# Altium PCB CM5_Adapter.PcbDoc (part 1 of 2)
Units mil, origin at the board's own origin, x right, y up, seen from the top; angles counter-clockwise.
Board outline 2180 x 1650 mil, 4 copper layers (Top Layer, Sig1, Sig2, Bottom Layer), stack 50.112 mil thick; 16 components, 251 nets, 1069 pads, 196 vias.
Unrouted connection lines stored in the file: 3.
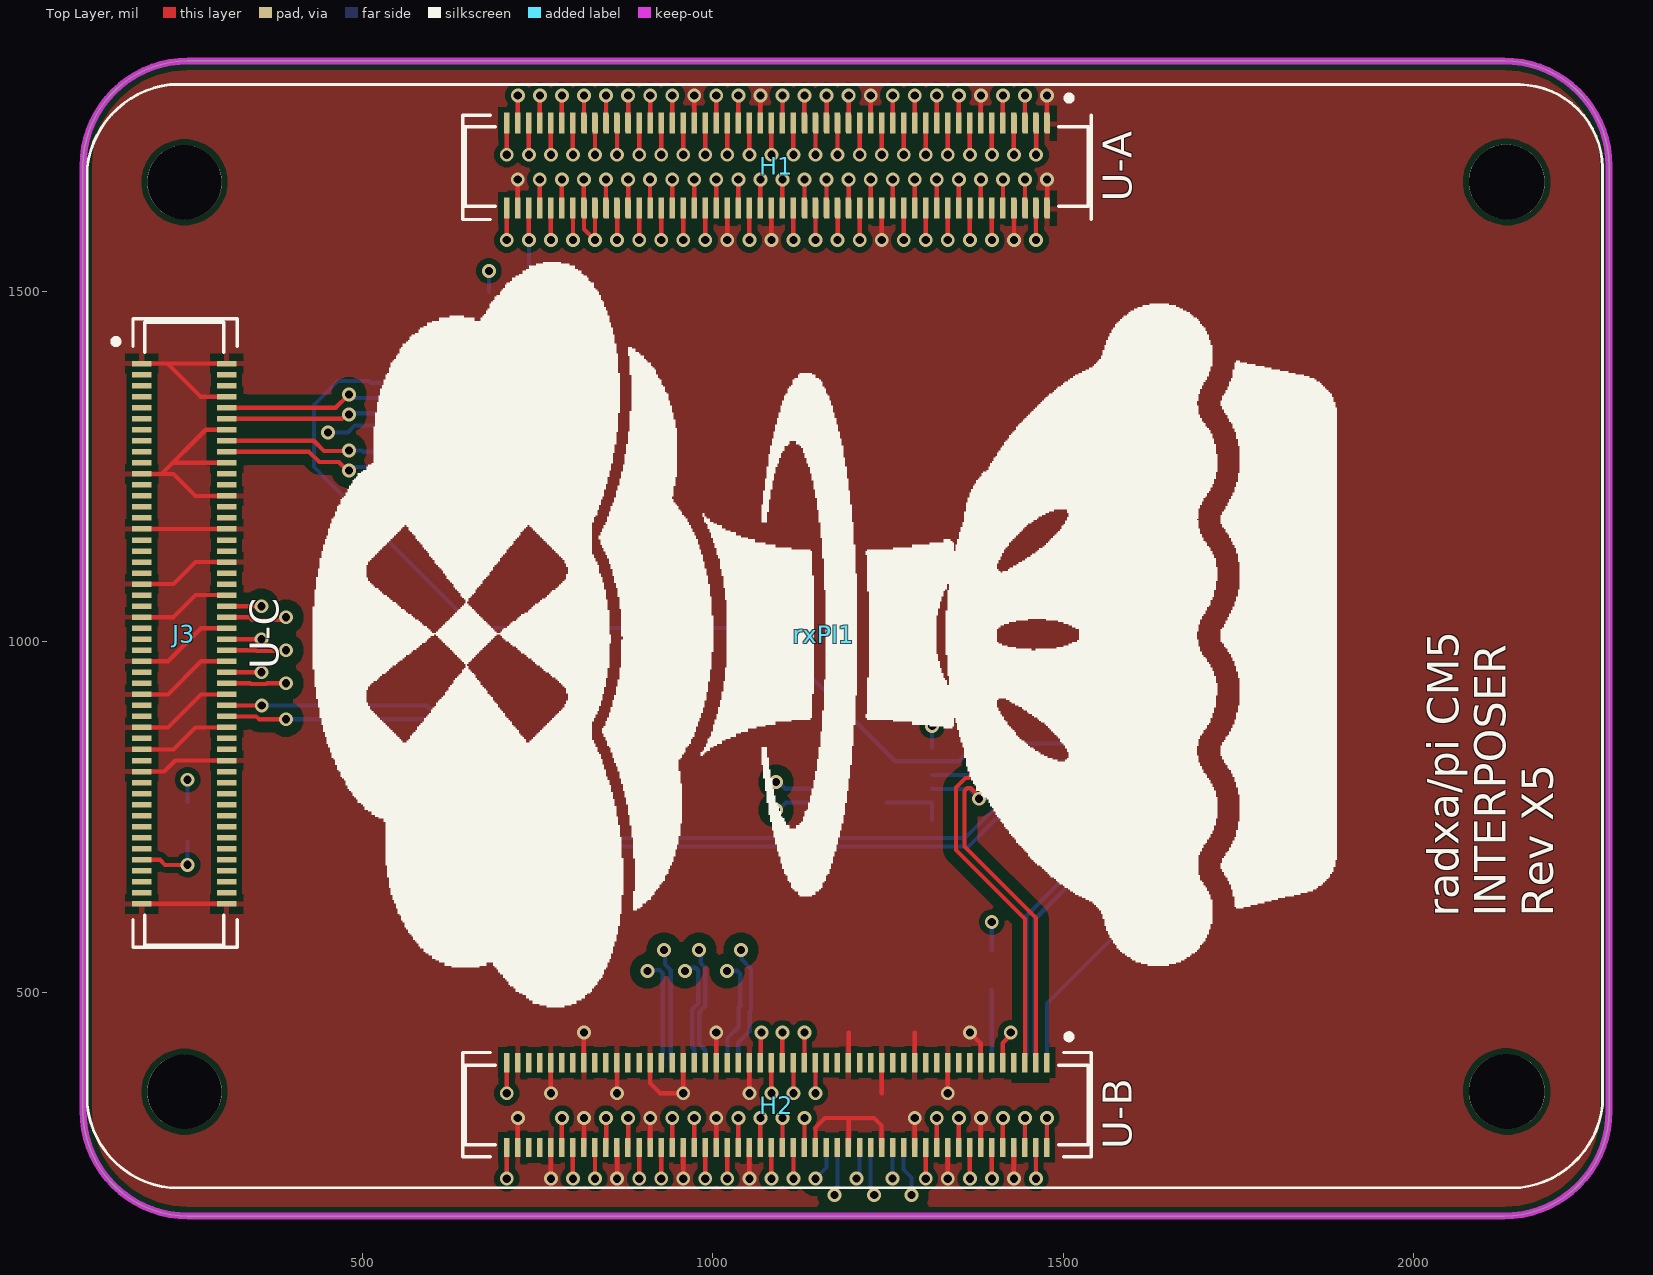
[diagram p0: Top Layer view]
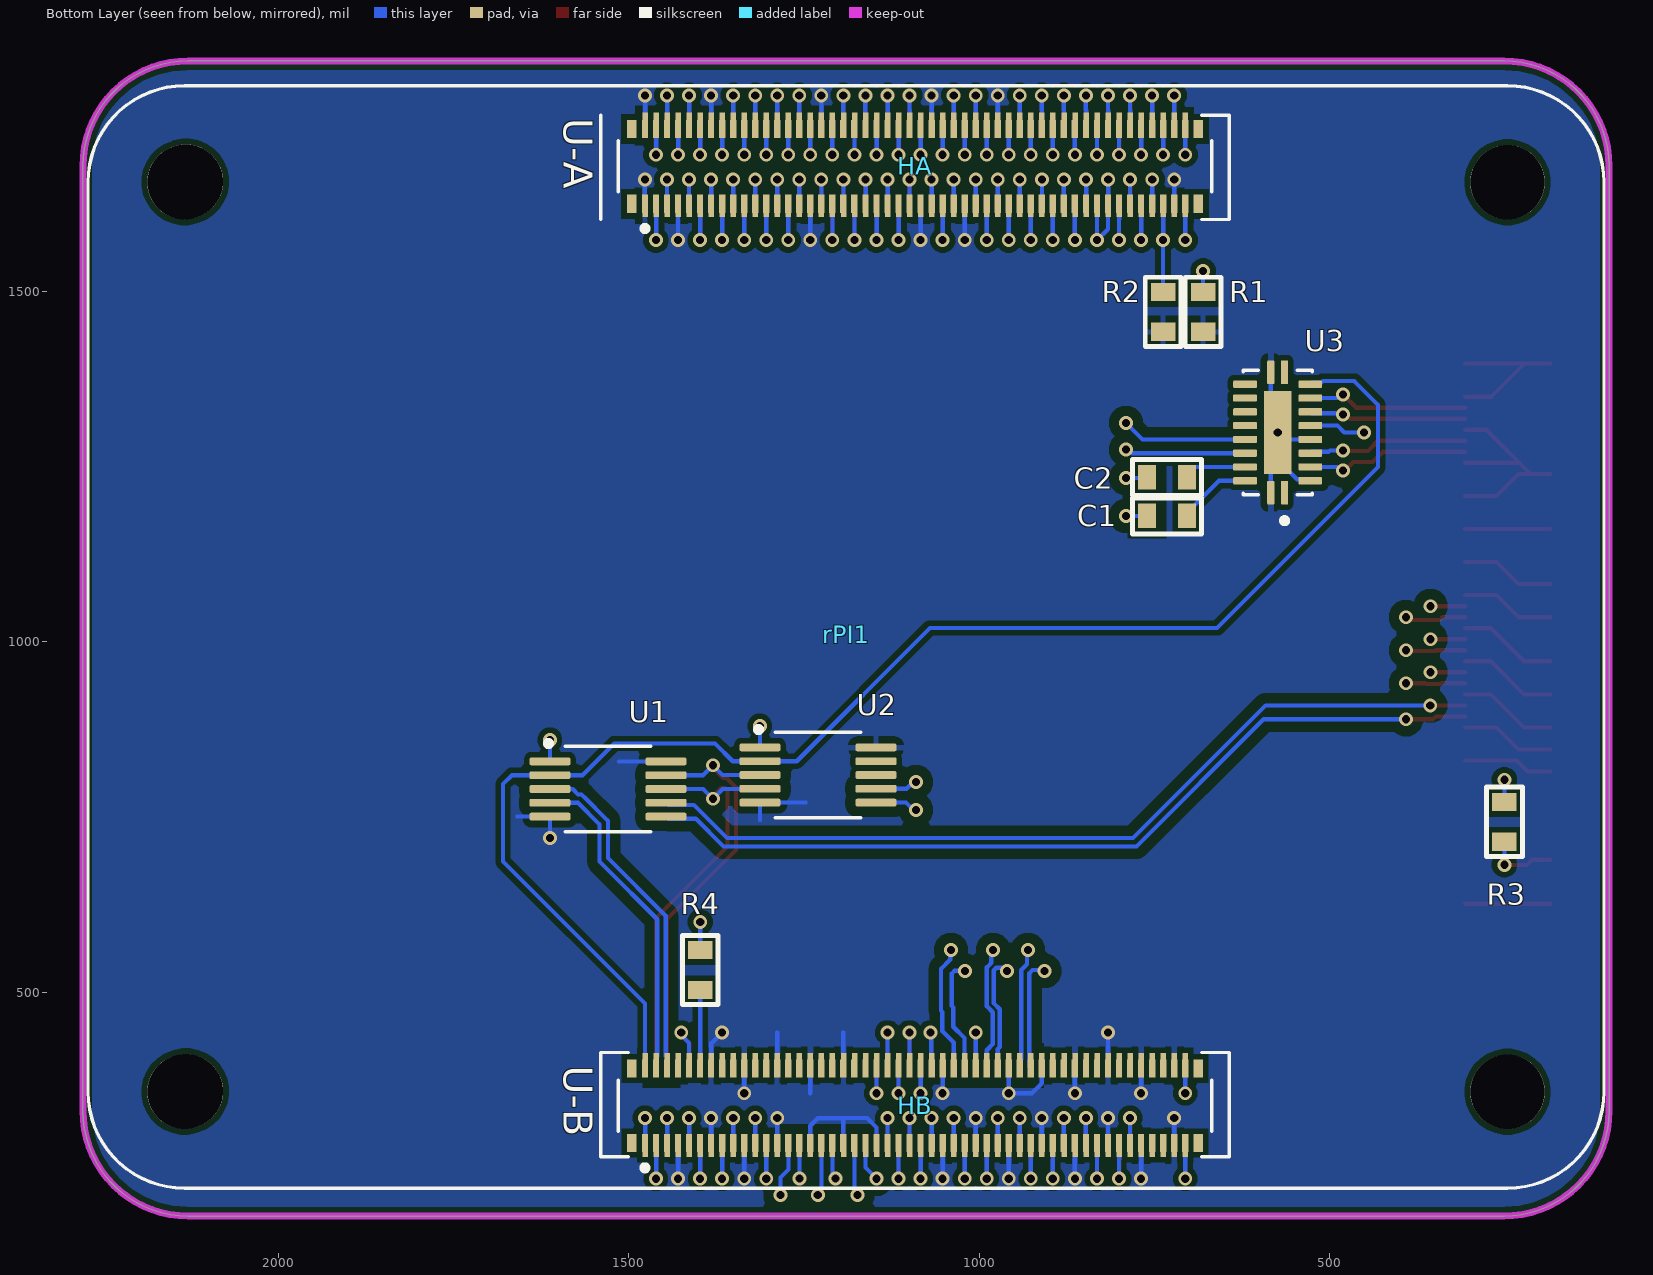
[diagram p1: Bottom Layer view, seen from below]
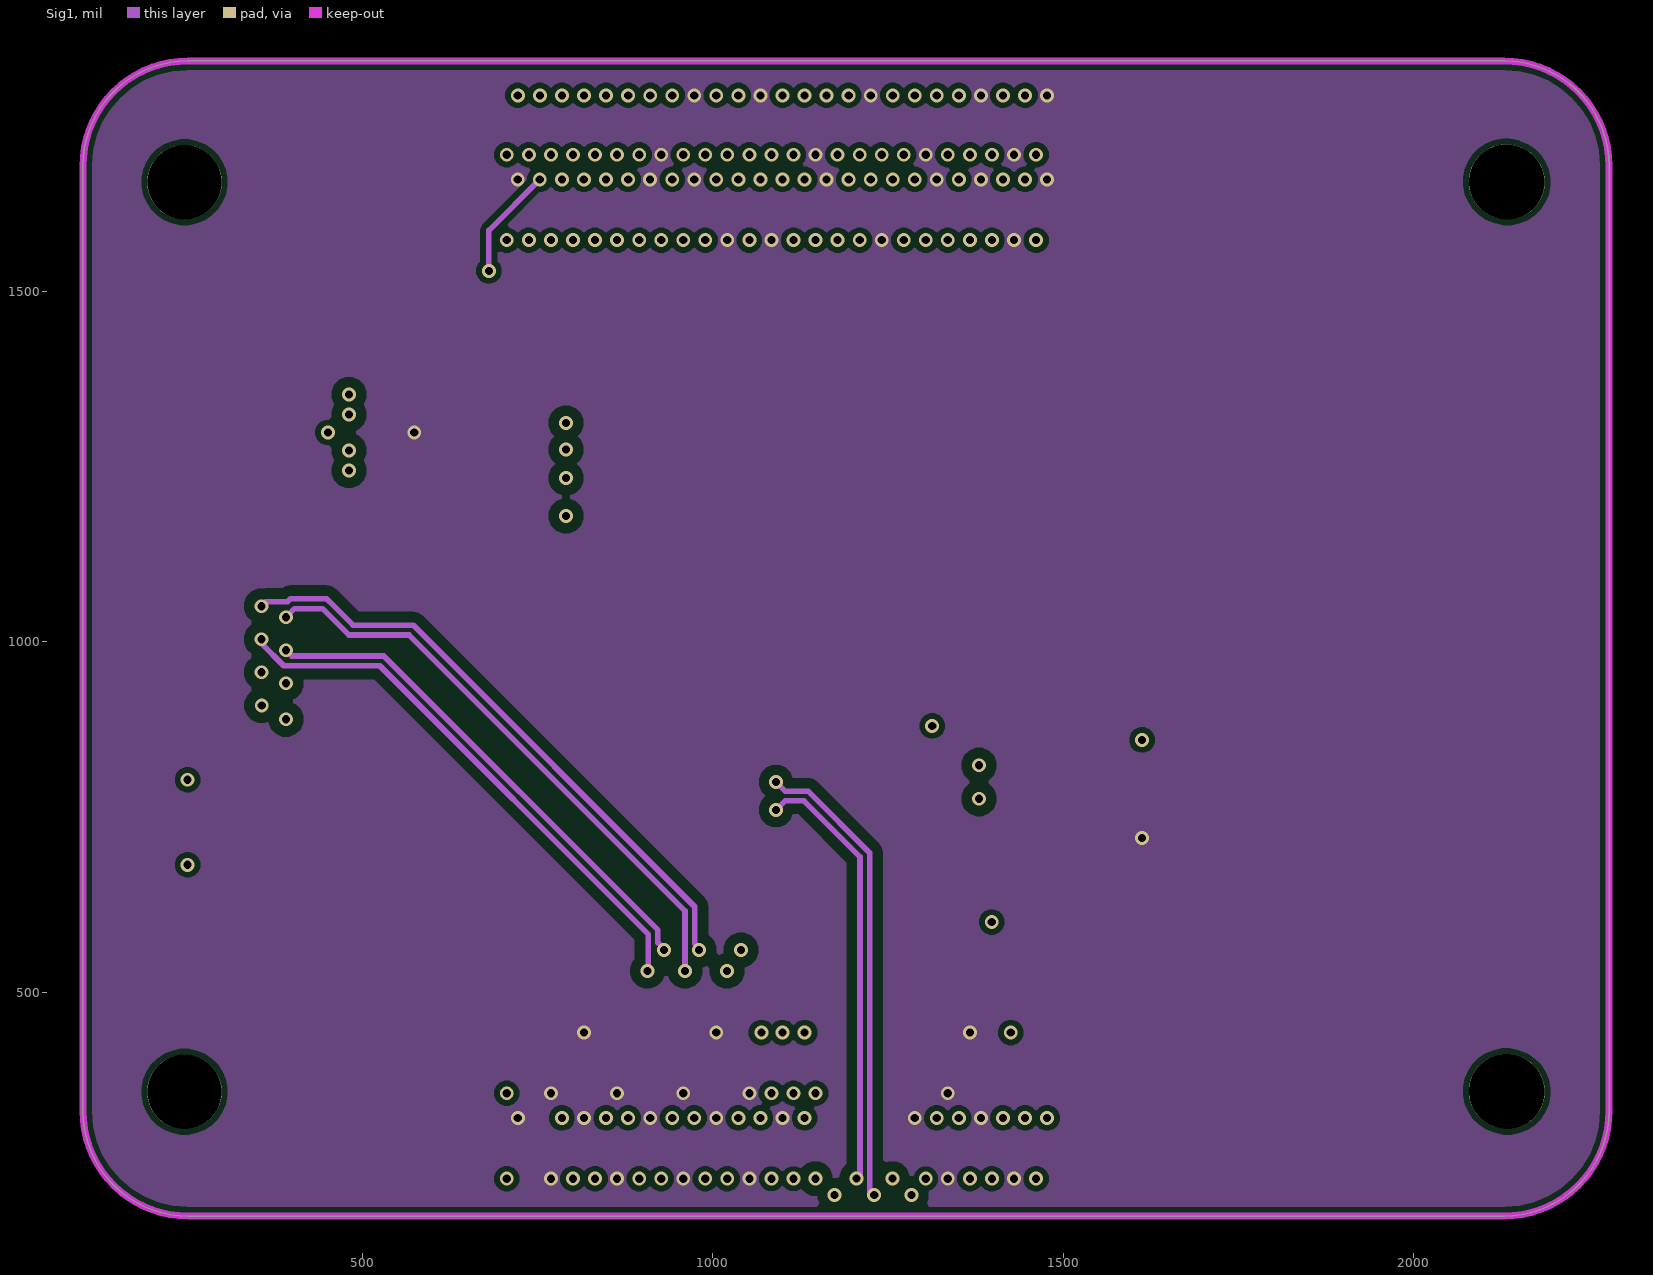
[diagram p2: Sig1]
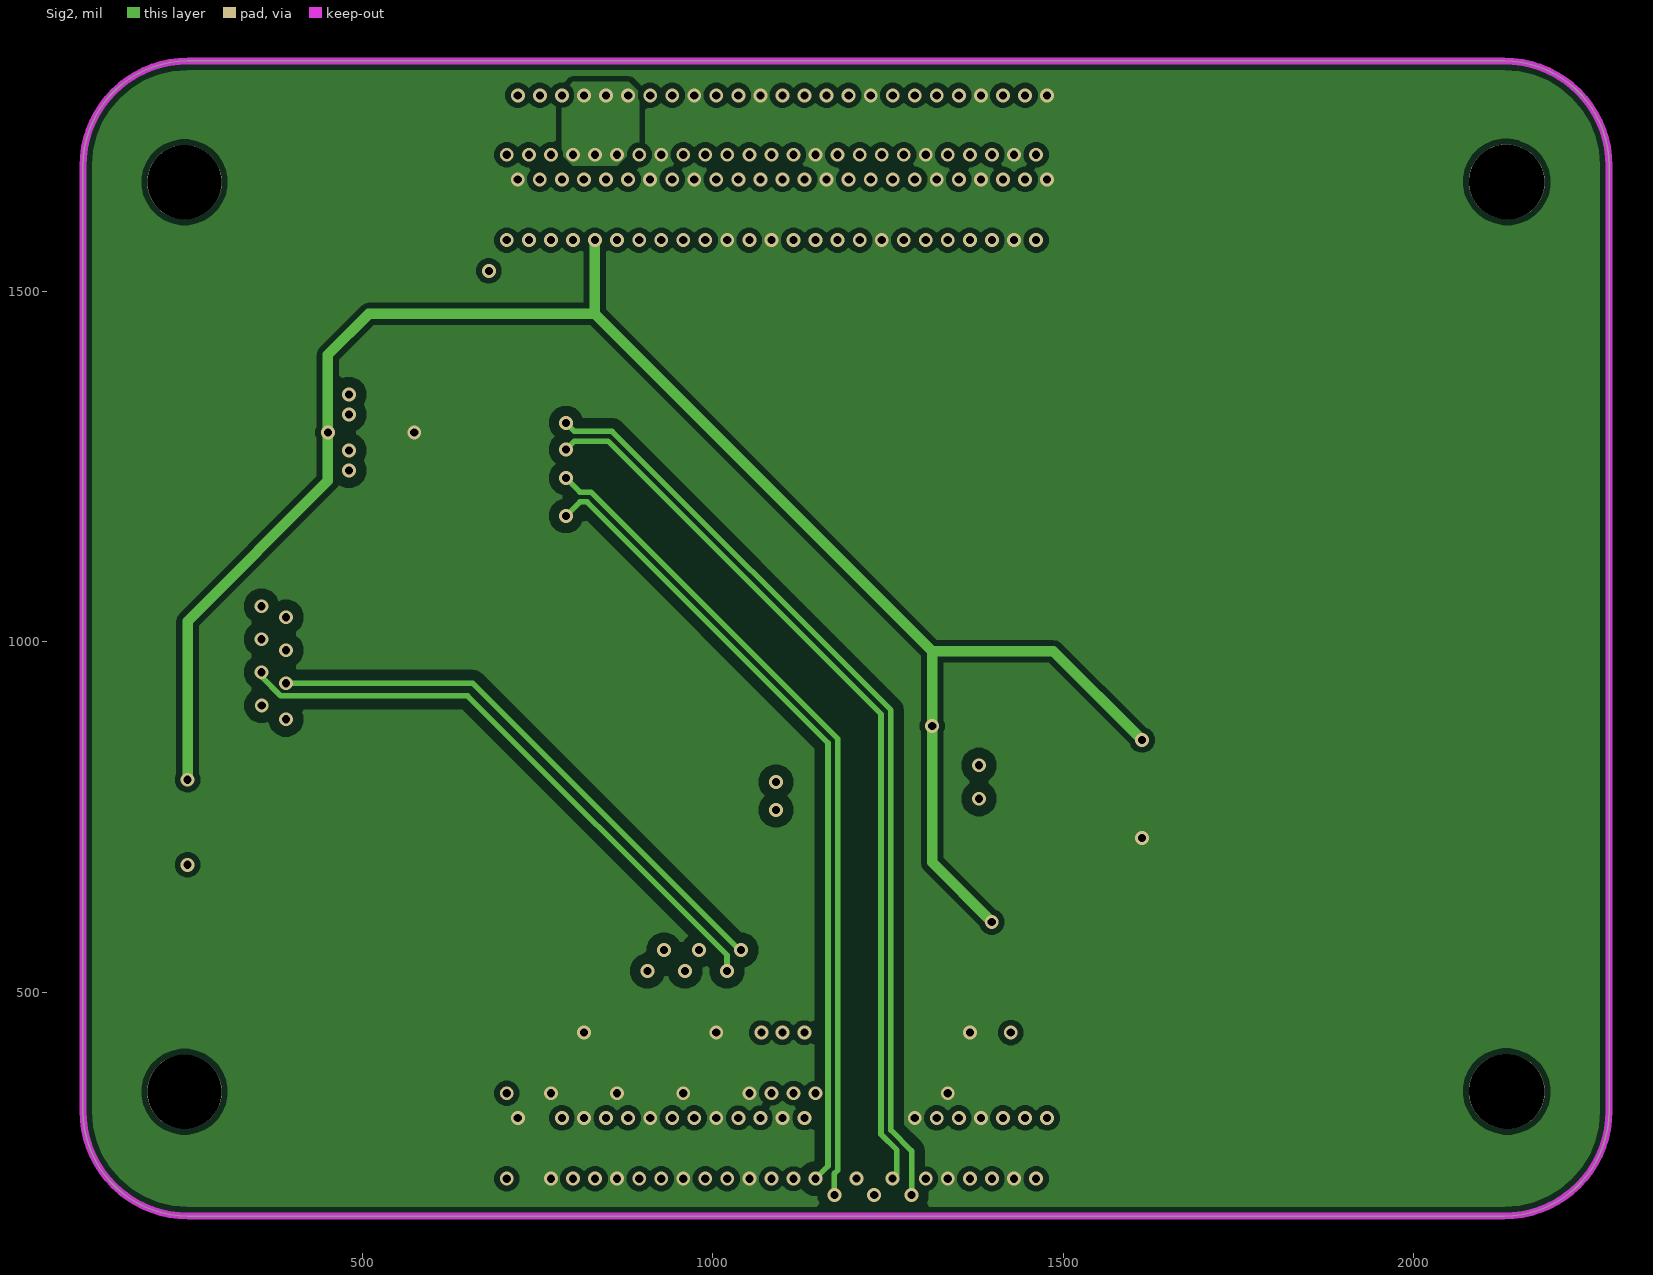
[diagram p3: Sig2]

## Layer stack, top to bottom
Top Solder: solder mask 0.4, Solder Resist, Dk 3.5
Top Layer: signal copper 1.378
Dielectric 1: prepreg 2.8, PP-006, Dk 4.1
Sig1: signal copper 1.378
Dielectric 3: core 39, Core-042, Dk 4.6
Sig2: signal copper 1.378
Dielectric 2: prepreg 2.8, PP-006, Dk 4.1
Bottom Layer: signal copper 1.378
Bottom Solder: solder mask 0.4, Solder Resist, Dk 3.5

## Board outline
100,330 100,1680 cw(c250,1680) 250,1830 2130,1830 cw(c2130,1680) 2280,1680 2280,330 cw(c2130,330) 2130,180 250,180 cw(c250,330)

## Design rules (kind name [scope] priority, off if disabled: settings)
Clearance DiffPairs_Clearance [InDifferentialPairClass('All Differential Pairs')] p1: gap=4 ignorepadtopadclearanceinfootprint=FALSE except(15: Arc-Fill Arc-Poly Arc-Region Track-Fill Track-Poly Track-Region SMDPad-Fill SMDPad-Poly SMDPad-Region THPad-Fill THPad-Poly THPad-Region Via-Fill Via-Poly Via-Region Fill-Fill Fill-Poly Fill-Region Poly-Poly Poly-Region Region-Region)
Clearance [All] p2: gap=8 ignorepadtopadclearanceinfootprint=FALSE except(0: SMDPad-SMDPad SMDPad-Hole Text-Hole; 5: Arc-SMDPad Track-SMDPad THPad-THPad; 5.91: Arc-Arc Arc-Track Track-Track; 7: Arc-Via Track-Via)
ComponentClearance [All] p1: gap=10 collisioncheckmode=3 verticalgap=10 showdistances=FALSE donotcheckwithout3dbody=TRUE
DiffPairsRouting [All] p1: maxlimit=10 minlimit=4 mostfreqgap=6 toplayer_minwidth=4 toplayer_maxwidth=15 toplayer_prefwidth=6 midlayer1_minwidth=4 midlayer1_maxwidth=15 midlayer1_prefwidth=8 midlayer2_minwidth=4 midlayer2_maxwidth=15 midlayer2_prefwidth=8 bottomlayer_minwidth=4 bottomlayer_maxwidth=15 bottomlayer_prefwidth=6 maxuncoupledlength=500
HoleSize [All] p1: absolutevalues=TRUE maxlimit=300 minlimit=1 maxpercent=80.000 minpercent=20.000
MatchedLengths [InDifferentialPairClass('All Differential Pairs')] p1: tolerance=10 checknetsindiffpair=TRUE checkdiffpairvsdiffpair=FALSE checkxsignals=FALSE checkothers=FALSE
MinimumSolderMaskSliver [All] p1: minsoldermaskwidth=5
PlaneClearance [All] p1: clearance=15
PlaneConnect [All] p1: planeconnectstyle=Direct reliefexpansion=20 reliefentries=4 reliefconductorwidth=10 reliefairgap=10
PolygonConnect [All] p1: thpad.connectstyle=Relief thpad.reliefconductorwidth=10 thpad.reliefentries=4 thpad.polygonreliefangle="45 Angle" thpad.airgapwidth=10 smdpad.connectstyle=Relief smdpad.reliefconductorwidth=8 smdpad.reliefentries=4 smdpad.polygonreliefangle="90 Angle" smdpad.airgapwidth=10 via.connectstyle=Direct via.reliefconductorwidth=10 via.reliefentries=4 via.polygonreliefangle="90 Angle" via.airgapwidth=10
RoutingVias [All] p1: holewidth=10 width=19 viastyle="Through Hole" minholewidth=10 minwidth=19 maxholewidth=16 maxwidth=30
ShortCircuit [All] p1: allowed=TRUE
SilkToSilkClearance [All] p1: silktosilkclearance=5
SilkToSolderMaskClearance [IsPad] p1: minsilkscreentomaskgap=1 clearancetoexposedcopper=TRUE
SolderMaskExpansion [All] p1: expansion=4 istentingtop=FALSE
SupplyNets "Schematic Supply Nets_69" [InNet('USB30_D_P')] p1: voltage=0.000
SupplyNets "Schematic Supply Nets_68" [InNet('USB_C_D_P')] p2: voltage=0.000
SupplyNets "Schematic Supply Nets_67" [InNet('USB_C_RX1_N')] p3: voltage=0.000
SupplyNets "Schematic Supply Nets_66" [InNet('USB20_HOST_D_N')] p4: voltage=0.000
SupplyNets "Schematic Supply Nets_65" [InNet('USB_C_RX1_P')] p5: voltage=0.000
SupplyNets "Schematic Supply Nets_64" [InNet('USB_C_TX1_N')] p6: voltage=0.000
SupplyNets "Schematic Supply Nets_54" [InNet('USB20_HOST_D_P')] p7: voltage=0.000
SupplyNets "Schematic Supply Nets_49" [InNet('USB_C_TX1_P')] p8: voltage=0.000
SupplyNets "Schematic Supply Nets_45" [InNet('USB30_D_N')] p9: voltage=0.000
SupplyNets "Schematic Supply Nets_33" [InNet('USB_C_D_N')] p10: voltage=0.000
SupplyNets "Schematic Supply Nets_63" [InNet('5VDC_BUS')] p11: voltage=0.000
SupplyNets "Schematic Supply Nets_62" [InNet('USB_OTG_D_N')] p12: voltage=0.000
SupplyNets "Schematic Supply Nets_10" [InNet('I2C_SDA')] p13: voltage=0.000
SupplyNets "Schematic Supply Nets_9" [InNet('I2C_SCL')] p14: voltage=0.000
SupplyNets "Schematic Supply Nets_4" [InNet('USB_OTG_D_P')] p15: voltage=0.000
SupplyNets "Schematic Supply Nets_59" [InNet('HDMI1_TX0_N')] p16: voltage=0.000
SupplyNets "Schematic Supply Nets_58" [InNet('USB_OTG_ID')] p17: voltage=0.000
SupplyNets "Schematic Supply Nets_57" [InNet('HDMI1_SDA')] p18: voltage=0.000
SupplyNets "Schematic Supply Nets_56" [InNet('HDMI0_CLK_P')] p19: voltage=0.000
SupplyNets "Schematic Supply Nets_55" [InNet('USB31_TX_P')] p20: voltage=0.000
SupplyNets "Schematic Supply Nets_51" [InNet('HDMI0_HOTPLUG')] p21: voltage=0.000
SupplyNets "Schematic Supply Nets_50" [InNet('HDMI0_TX1_P')] p22: voltage=0.000
SupplyNets "Schematic Supply Nets_48" [InNet('HDMI1_TX1_P')] p23: voltage=0.000
SupplyNets "Schematic Supply Nets_47" [InNet('Res104')] p24: voltage=0.000
SupplyNets "Schematic Supply Nets_44" [InNet('USB31_RX_P')] p25: voltage=0.000
SupplyNets "Schematic Supply Nets_43" [InNet('USB31_D_N')] p26: voltage=0.000
SupplyNets "Schematic Supply Nets_42" [InNet('Res106')] p27: voltage=0.000
SupplyNets "Schematic Supply Nets_41" [InNet('HDMI0_CEC')] p28: voltage=0.000
SupplyNets "Schematic Supply Nets_40" [InNet('USB30_TX1_N')] p29: voltage=0.000
SupplyNets "Schematic Supply Nets_39" [InNet('HDMI0_SDA')] p30: voltage=0.000
SupplyNets "Schematic Supply Nets_38" [InNet('USB31_TX_N')] p31: voltage=0.000
SupplyNets "Schematic Supply Nets_37" [InNet('HDMI0_TX1_N')] p32: voltage=0.000
SupplyNets "Schematic Supply Nets_36" [InNet('USB30_RX1_N')] p33: voltage=0.000
SupplyNets "Schematic Supply Nets_35" [InNet('HDMI0_SCL')] p34: voltage=0.000
SupplyNets "Schematic Supply Nets_32" [InNet('HDMI0_TX0_P')] p35: voltage=0.000
SupplyNets "Schematic Supply Nets_31" [InNet('HDMI1_CLK_P')] p36: voltage=0.000
SupplyNets "Schematic Supply Nets_30" [InNet('HDMI1_HOTPLUG')] p37: voltage=0.000
SupplyNets "Schematic Supply Nets_29" [InNet('HDMI1_TX0_P')] p38: voltage=0.000
SupplyNets "Schematic Supply Nets_27" [InNet('PCIe_CLK_nREQ')] p39: voltage=0.000
SupplyNets "Schematic Supply Nets_26" [InNet('USB31_D_P')] p40: voltage=0.000
SupplyNets "Schematic Supply Nets_25" [InNet('USB30_TX1_P')] p41: voltage=0.000
SupplyNets "Schematic Supply Nets_24" [InNet('VCC_3V3_S3')] p42: voltage=0.000
SupplyNets "Schematic Supply Nets_23" [InNet('HDMI1_TX2_N')] p43: voltage=0.000
SupplyNets "Schematic Supply Nets_22" [InNet('HDMI1_TX1_N')] p44: voltage=0.000
SupplyNets "Schematic Supply Nets_21" [InNet('HDMI1_CEC')] p45: voltage=0.000
SupplyNets "Schematic Supply Nets_20" [InNet('HDMI0_TX2_P')] p46: voltage=0.000
SupplyNets "Schematic Supply Nets_19" [InNet('USB31_RX_N')] p47: voltage=0.000
SupplyNets "Schematic Supply Nets_18" [InNet('HDMI0_TX0_N')] p48: voltage=0.000
SupplyNets "Schematic Supply Nets_17" [InNet('HDMI1_SCL')] p49: voltage=0.000
SupplyNets "Schematic Supply Nets_16" [InNet('PCIe_nRST')] p50: voltage=0.000
SupplyNets "Schematic Supply Nets_15" [InNet('HDMI1_TX2_P')] p51: voltage=0.000
SupplyNets "Schematic Supply Nets_14" [InNet('HDMI1_CLK_N')] p52: voltage=0.000
SupplyNets "Schematic Supply Nets_13" [InNet('HDMI0_TX2_N')] p53: voltage=0.000
SupplyNets "Schematic Supply Nets_12" [InNet('HDMI0_CLK_N')] p54: voltage=0.000
SupplyNets "Schematic Supply Nets_11" [InNet('USB30_RX1_P')] p55: voltage=0.000
SupplyNets "Schematic Supply Nets_8" [InNet('PCIe_TX_N')] p56: voltage=0.000
SupplyNets "Schematic Supply Nets_6" [InNet('PCIe_RX_P')] p57: voltage=0.000
SupplyNets "Schematic Supply Nets_5" [InNet('GND')] p58: voltage=0.000
SupplyNets "Schematic Supply Nets_3" [InNet('PCIe_CLK_P')] p59: voltage=0.000
SupplyNets "Schematic Supply Nets_2" [InNet('PCIe_RX_N')] p60: voltage=0.000
SupplyNets "Schematic Supply Nets_1" [InNet('PCIe_CLK_N')] p61: voltage=0.000
SupplyNets "Schematic Supply Nets" [InNet('PCIe_TX_P')] p62: voltage=0.000
Width [All] p1: maxlimit=300 minlimit=4 preferedwidth=8 toplayer_prefwidth=6 bottomlayer_prefwidth=6 minimp=50.000000 maximp=50.000000 favimp=50.000000
21 further rules are at their usual default settings.

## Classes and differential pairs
differential pair USB_C_TX1: +USB_C_TX1_P -USB_C_TX1_N
differential pair USB_C_RX1: +USB_C_RX1_P -USB_C_RX1_N
differential pair USB_C_D: +USB_C_D_P -USB_C_D_N
differential pair USB30_D: +USB30_D_P -USB30_D_N
differential pair USB20_HOST_D: +USB20_HOST_D_P -USB20_HOST_D_N
differential pair USB_OTG_D: +USB_OTG_D_P -USB_OTG_D_N
differential pair USB31_TX: +USB31_TX_P -USB31_TX_N
differential pair USB31_RX: +USB31_RX_P -USB31_RX_N
differential pair USB31_D: +USB31_D_P -USB31_D_N
differential pair USB30_TX1: +USB30_TX1_P -USB30_TX1_N
differential pair USB30_RX1: +USB30_RX1_P -USB30_RX1_N

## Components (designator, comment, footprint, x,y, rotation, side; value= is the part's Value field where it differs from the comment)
C1 "Generic Capacitor" 0603 703,1180 r0 bottom value=220nF
C2 "Generic Capacitor" 0603 703,1235.06 r0 bottom value=220nF
H1 "100P RCPT" DF40C-100DS-0.4V(51) 1091.38,1679.18 r0 top locked
H2 "100P MEZZ" DF40C-100DS-0.4V(51) 1091.19,338.46 r0 top locked
HA "100P MEZZ" DF40C-100DP-0.4V(51) 1091.38,1679.18 r180 bottom locked
HB "100P RCPT" DF40C-100DP-0.4V(51) 1091.38,337.53 r180 bottom locked
J3 "100P RCPT" DF40C-100DS-0.4V(51) 244.76,1011.78 r90 top locked
R1 "Generic Resistor" 0603 679.96,1500 r270 bottom value=5.1K
R2 "Generic Resistor" 0603 737.05,1500 r270 bottom value=5.1K
R3 "Generic Resistor" 0603 249.47,771.62 r270 bottom value=0
R4 "Generic Resistor" 0603 1398.28,560 r270 bottom value=100
rPI1 "CM5 Landing pads" "rP-200P-CM-REP (top)" 1190,1010 r270 bottom locked
rxPI1 "RxCM5 Landing pads" RX-300P-CM-FTPD 1158.52,1010 r90 top locked
U1 "U2 MUX" MSOP-10 1530,790 r180 bottom
U2 "U2 MUX" MSOP-10 1230,810 r180 bottom
U3 "USB3 Mux" QFN50P450X250X100-21N 573.35,1299.21 r0 bottom

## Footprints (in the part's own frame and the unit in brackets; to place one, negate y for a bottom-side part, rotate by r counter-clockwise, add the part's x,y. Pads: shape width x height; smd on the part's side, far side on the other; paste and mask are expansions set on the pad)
0603 [mil] "Common Chip Capacitor 0603 (1608 Metric)"
  rect 26x35 smd: 1(0,0) 2(57,0)
  silkscreen extent -21,-26 78,26, body extent -2,-16 59,16, height 17
DF40C-100DP-0.4V(51) [mm]
  rect 0.23x0.66 smd: 1(-9.8,-1.355) 2(-9.8,1.355) 3(-9.4,-1.355) 4(-9.4,1.355) 5(-9,-1.355) 6(-9,1.355) 7(-8.6,-1.355) 8(-8.6,1.355) 9(-8.2,-1.355) 10(-8.2,1.355) 11(-7.8,-1.355) 12(-7.8,1.355) 13(-7.4,-1.355) 14(-7.4,1.355) 15(-7,-1.355) 16(-7,1.355) 17(-6.6,-1.355) 18(-6.6,1.355) 19(-6.2,-1.355) 20(-6.2,1.355) 21(-5.8,-1.355) 22(-5.8,1.355) 23(-5.4,-1.355) 24(-5.4,1.355) 25(-5,-1.355) 26(-5,1.355) 27(-4.6,-1.355) 28(-4.6,1.355) 29(-4.2,-1.355) 30(-4.2,1.355) 31(-3.8,-1.355) 32(-3.8,1.355) 33(-3.4,-1.355) 34(-3.4,1.355) 35(-3,-1.355) 36(-3,1.355) 37(-2.6,-1.355) 38(-2.6,1.355) 39(-2.2,-1.355) 40(-2.2,1.355) 41(-1.8,-1.355) 42(-1.8,1.355) 43(-1.4,-1.355) 44(-1.4,1.355) 45(-1,-1.355) 46(-1,1.355) 47(-0.6,-1.355) 48(-0.6,1.355) 49(-0.2,-1.355) 50(-0.2,1.355) 51(0.2,-1.355) 52(0.2,1.355) 53(0.6,-1.355) 54(0.6,1.355) 55(1,-1.355) 56(1,1.355) 57(1.4,-1.355) 58(1.4,1.355) 59(1.8,-1.355) 60(1.8,1.355) 61(2.2,-1.355) 62(2.2,1.355) 63(2.6,-1.355) 64(2.6,1.355) 65(3,-1.355) 66(3,1.355) 67(3.4,-1.355) 68(3.4,1.355) 69(3.8,-1.355) 70(3.8,1.355) 71(4.2,-1.355) 72(4.2,1.355) 73(4.6,-1.355) 74(4.6,1.355) 75(5,-1.355) 76(5,1.355) 77(5.4,-1.355) 78(5.4,1.355) 79(5.8,-1.355) 80(5.8,1.355) 81(6.2,-1.355) 82(6.2,1.355) 83(6.6,-1.355) 84(6.6,1.355) 85(7,-1.355) 86(7,1.355) 87(7.4,-1.355) 88(7.4,1.355) 89(7.8,-1.355) 90(7.8,1.355) 91(8.2,-1.355) 92(8.2,1.355) 93(8.6,-1.355) 94(8.6,1.355) 95(9,-1.355) 96(9,1.355) 97(9.4,-1.355) 98(9.4,1.355) 99(9.8,-1.355) 100(9.8,1.355)
  rect 0.35x0.66 smd: S1(-10.275,-1.355) S2(-10.275,1.355) S3(10.275,-1.355) S4(10.275,1.355)
  silkscreen extent -10.76,-2.35 10.76,0.92, body extent -10.76,-1.52 10.76,1.45, height 1.13
DF40C-100DS-0.4V(51) [mm] "Hirose 100pos RCPT (Short)"
  rect 0.2x0.7 smd paste-1: 1(9.8,1.54) 2(9.8,-1.54) 3(9.4,1.54) 4(9.4,-1.54) 5(9,1.54) 6(9,-1.54) 7(8.6,1.54) 8(8.6,-1.54) 9(8.2,1.54) 10(8.2,-1.54) 11(7.8,1.54) 12(7.8,-1.54) 13(7.4,1.54) 14(7.4,-1.54) 15(7,1.54) 16(7,-1.54) 17(6.6,1.54) 18(6.6,-1.54) 19(6.2,1.54) 20(6.2,-1.54) 21(5.8,1.54) 22(5.8,-1.54) 23(5.4,1.54) 24(5.4,-1.54) 25(5,1.54) 26(5,-1.54) 27(4.6,1.54) 28(4.6,-1.54) 29(4.2,1.54) 30(4.2,-1.54) 31(3.8,1.54) 32(3.8,-1.54) 33(3.4,1.54) 34(3.4,-1.54) 35(3,1.54) 36(3,-1.54) 37(2.6,1.54) 38(2.6,-1.54) 39(2.2,1.54) 40(2.2,-1.54) 41(1.8,1.54) 42(1.8,-1.54) 43(1.4,1.54) 44(1.4,-1.54) 45(1,1.54) 46(1,-1.54) 47(0.6,1.54) 48(0.6,-1.54) 49(0.2,1.54) 50(0.2,-1.54) 51(-0.2,1.54) 52(-0.2,-1.54) 53(-0.6,1.54) 54(-0.6,-1.54) 55(-1,1.54) 56(-1,-1.54) 57(-1.4,1.54) 58(-1.4,-1.54) 59(-1.8,1.54) 60(-1.8,-1.54) 61(-2.2,1.54) 62(-2.2,-1.54) 63(-2.6,1.54) 64(-2.6,-1.54) 65(-3,1.54) 66(-3,-1.54) 67(-3.4,1.54) 68(-3.4,-1.54) 69(-3.8,1.54) 70(-3.8,-1.54) 71(-4.2,1.54) 72(-4.2,-1.54) 73(-4.6,1.54) 74(-4.6,-1.54) 75(-5,1.54) 76(-5,-1.54) 77(-5.4,1.54) 78(-5.4,-1.54) 79(-5.8,1.54) 80(-5.8,-1.54) 81(-6.2,1.54) 82(-6.2,-1.54) 83(-6.6,1.54) 84(-6.6,-1.54) 85(-7,1.54) 86(-7,-1.54) 87(-7.4,1.54) 88(-7.4,-1.54) 89(-7.8,1.54) 90(-7.8,-1.54) 91(-8.2,1.54) 92(-8.2,-1.54) 93(-8.6,1.54) 94(-8.6,-1.54) 95(-9,1.54) 96(-9,-1.54) 97(-9.4,1.54) 98(-9.4,-1.54) 99(-9.8,1.54) 100(-9.8,-1.54)
  silkscreen extent -11.3,-1.44 11.3,2.58, body extent -11.3,-1.69 11.3,1.69, height 1.6
MSOP-10 [mm] "10-TFSOP, 10-MSOP (0.118\", 3.00mm Width)"
  rrect50% 1.5x0.28 smd: 1(-2.105,1) 2(-2.105,0.5) 3(-2.105,0) 4(-2.105,-0.5) 5(-2.105,-1) 6(2.105,-1) 7(2.105,-0.5) 8(2.105,0) 9(2.105,0.5) 10(2.105,1)
  silkscreen extent -2.26,-1.55 1.55,1.75, body extent -2.45,-1.5 2.45,1.5, height 1.1
QFN50P450X250X100-21N [mm]
  rrect25% 0.26x0.86 smd: 1(-0.25,2.185) 10(-0.25,-2.185) 11(0.25,-2.185) 20(0.25,2.185)
  rrect25% 0.86x0.26 smd: 2(-1.185,1.75) 3(-1.185,1.25) 4(-1.185,0.75) 5(-1.185,0.25) 6(-1.185,-0.25) 7(-1.185,-0.75) 8(-1.185,-1.25) 9(-1.185,-1.75) 12(1.185,-1.75) 13(1.185,-1.25) 14(1.185,-0.75) 15(1.185,-0.25) 16(1.185,0.25) 17(1.185,0.75) 18(1.185,1.25) 19(1.185,1.75)
  rect 1x3 smd paste-3: 21(0,0)
  silkscreen extent -1.25,-2.25 1.25,3.3, body extent -1.25,-2.25 1.25,2.25, height 1
"rP-200P-CM-REP (top)" [mm] "Landing-Pad for 200-pin compute modules"
  rect 0.7x0.2 smd mask+0: 1(-18.597,-7.29) 2(-15.517,-7.29) 3(-18.597,-6.89) 4(-15.517,-6.89) 5(-18.597,-6.49) 6(-15.517,-6.49) 7(-18.597,-6.09) 8(-15.517,-6.09) 9(-18.597,-5.69) 10(-15.517,-5.69) 11(-18.597,-5.29) 12(-15.517,-5.29) 13(-18.597,-4.89) 14(-15.517,-4.89) 15(-18.597,-4.49) 16(-15.517,-4.49) 17(-18.597,-4.09) 18(-15.517,-4.09) 19(-18.597,-3.69) 20(-15.517,-3.69) 21(-18.597,-3.29) 22(-15.517,-3.29) 23(-18.597,-2.89) 24(-15.517,-2.89) 25(-18.597,-2.49) 26(-15.517,-2.49) 27(-18.597,-2.09) 28(-15.517,-2.09) 29(-18.597,-1.69) 30(-15.517,-1.69) 31(-18.597,-1.29) 32(-15.517,-1.29) 33(-18.597,-0.89) 34(-15.517,-0.89) 35(-18.597,-0.49) 36(-15.517,-0.49) 37(-18.597,-0.09) 38(-15.517,-0.09) 39(-18.597,0.31) 40(-15.517,0.31) 41(-18.597,0.71) 42(-15.517,0.71) 43(-18.597,1.11) 44(-15.517,1.11) 45(-18.597,1.51) 46(-15.517,1.51) 47(-18.597,1.91) 48(-15.517,1.91) 49(-18.597,2.31) 50(-15.517,2.31) 51(-18.597,2.71) 52(-15.517,2.71) 53(-18.597,3.11) 54(-15.517,3.11) 55(-18.597,3.51) 56(-15.517,3.51) 57(-18.597,3.91) 58(-15.517,3.91) 59(-18.597,4.31) 60(-15.517,4.31) 61(-18.597,4.71) 62(-15.517,4.71) 63(-18.597,5.11) 64(-15.517,5.11) 65(-18.597,5.51) 66(-15.517,5.51) 67(-18.597,5.91) 68(-15.517,5.91) 69(-18.597,6.31) 70(-15.517,6.31) 71(-18.597,6.71) 72(-15.517,6.71) 73(-18.597,7.11) 74(-15.517,7.11) 75(-18.597,7.51) 76(-15.517,7.51) 77(-18.597,7.91) 78(-15.517,7.91) 79(-18.597,8.31) 80(-15.517,8.31) 81(-18.597,8.71) 82(-15.517,8.71) 83(-18.597,9.11) 84(-15.517,9.11) 85(-18.597,9.51) 86(-15.517,9.51) 87(-18.597,9.91) 88(-15.517,9.91) 89(-18.597,10.31) 90(-15.517,10.31) 91(-18.597,10.71) 92(-15.517,10.71) 93(-18.597,11.11) 94(-15.517,11.11) 95(-18.597,11.51) 96(-15.517,11.51) 97(-18.597,11.91) 98(-15.517,11.91) 99(-18.597,12.31) 100(-15.517,12.31) 101(15.517,-7.29) 102(18.597,-7.29) 103(15.517,-6.89) 104(18.597,-6.89) 105(15.517,-6.49) 106(18.597,-6.49) 107(15.517,-6.09) 108(18.597,-6.09) 109(15.517,-5.69) 110(18.597,-5.69) 111(15.517,-5.29) 112(18.597,-5.29) 113(15.517,-4.89) 114(18.597,-4.89) 115(15.517,-4.49) 116(18.597,-4.49) 117(15.517,-4.09) 118(18.597,-4.09) 119(15.517,-3.69) 120(18.597,-3.69) 121(15.517,-3.29) 122(18.597,-3.29) 123(15.517,-2.89) 124(18.597,-2.89) 125(15.517,-2.49) 126(18.597,-2.49) 127(15.517,-2.09) 128(18.597,-2.09) 129(15.517,-1.69) 130(18.597,-1.69) 131(15.517,-1.29) 132(18.597,-1.29) 133(15.517,-0.89) 134(18.597,-0.89) 135(15.517,-0.49) 136(18.597,-0.49) 137(15.517,-0.09) 138(18.597,-0.09) 139(15.517,0.31) 140(18.597,0.31) 141(15.517,0.71) 142(18.597,0.71) 143(15.517,1.11) 144(18.597,1.11) 145(15.517,1.51) 146(18.597,1.51) 147(15.517,1.91) 148(18.597,1.91) 149(15.517,2.31) 150(18.597,2.31) 151(15.517,2.71) 152(18.597,2.71) 153(15.517,3.11) 154(18.597,3.11) 155(15.517,3.51) 156(18.597,3.51) 157(15.517,3.91) 158(18.597,3.91) 159(15.517,4.31) 160(18.597,4.31) 161(15.517,4.71) 162(18.597,4.71) 163(15.517,5.11) 164(18.597,5.11) 165(15.517,5.51) 166(18.597,5.51) 167(15.517,5.91) 168(18.597,5.91) 169(15.517,6.31) 170(18.597,6.31) 171(15.517,6.71) 172(18.597,6.71) 173(15.517,7.11) 174(18.597,7.11) 175(15.517,7.51) 176(18.597,7.51) 177(15.517,7.91) 178(18.597,7.91) 179(15.517,8.31) 180(18.597,8.31) 181(15.517,8.71) 182(18.597,8.71) 183(15.517,9.11) 184(18.597,9.11) 185(15.517,9.51) 186(18.597,9.51) 187(15.517,9.91) 188(18.597,9.91) 189(15.517,10.31) 190(18.597,10.31) 191(15.517,10.71) 192(18.597,10.71) 193(15.517,11.11) 194(18.597,11.11) 195(15.517,11.51) 196(18.597,11.51) 197(15.517,11.91) 198(18.597,11.91) 199(15.517,12.31) 200(18.597,12.31)
  round 2.7 hole 2.7 paste-2539.97 mask+1.7: Un1(-16.427,24) Un2(16.573,-24) Un3(16.573,24) Un4(-16.427,-24)
  silkscreen extent -19.93,-27.5 20.07,27.5
RX-300P-CM-FTPD [mm] "Landing-Pad for 300-pin radxa compute modules"
  rect 0.7x0.2 smd mask+0: 1(18.597,-8.09) 2(15.517,-8.09) 3(18.597,-7.69) 4(15.517,-7.69) 5(18.597,-7.29) 6(15.517,-7.29) 7(18.597,-6.89) 8(15.517,-6.89) 9(18.597,-6.49) 10(15.517,-6.49) 11(18.597,-6.09) 12(15.517,-6.09) 13(18.597,-5.69) 14(15.517,-5.69) 15(18.597,-5.29) 16(15.517,-5.29) 17(18.597,-4.89) 18(15.517,-4.89) 19(18.597,-4.49) 20(15.517,-4.49) 21(18.597,-4.09) 22(15.517,-4.09) 23(18.597,-3.69) 24(15.517,-3.69) 25(18.597,-3.29) 26(15.517,-3.29) 27(18.597,-2.89) 28(15.517,-2.89) 29(18.597,-2.49) 30(15.517,-2.49) 31(18.597,-2.09) 32(15.517,-2.09) 33(18.597,-1.69) 34(15.517,-1.69) 35(18.597,-1.29) 36(15.517,-1.29) 37(18.597,-0.89) 38(15.517,-0.89) 39(18.597,-0.49) 40(15.517,-0.49) 41(18.597,-0.09) 42(15.517,-0.09) 43(18.597,0.31) 44(15.517,0.31) 45(18.597,0.71) 46(15.517,0.71) 47(18.597,1.11) 48(15.517,1.11) 49(18.597,1.51) 50(15.517,1.51) 51(18.597,1.91) 52(15.517,1.91) 53(18.597,2.31) 54(15.517,2.31) 55(18.597,2.71) 56(15.517,2.71) 57(18.597,3.11) 58(15.517,3.11) 59(18.597,3.51) 60(15.517,3.51) 61(18.597,3.91) 62(15.517,3.91) 63(18.597,4.31) 64(15.517,4.31) 65(18.597,4.71) 66(15.517,4.71) 67(18.597,5.11) 68(15.517,5.11) 69(18.597,5.51) 70(15.517,5.51) 71(18.597,5.91) 72(15.517,5.91) 73(18.597,6.31) 74(15.517,6.31) 75(18.597,6.71) 76(15.517,6.71) 77(18.597,7.11) 78(15.517,7.11) 79(18.597,7.51) 80(15.517,7.51) 81(18.597,7.91) 82(15.517,7.91) 83(18.597,8.31) 84(15.517,8.31) 85(18.597,8.71) 86(15.517,8.71) 87(18.597,9.11) 88(15.517,9.11) 89(18.597,9.51) 90(15.517,9.51) 91(18.597,9.91) 92(15.517,9.91) 93(18.597,10.31) 94(15.517,10.31) 95(18.597,10.71) 96(15.517,10.71) 97(18.597,11.11) 98(15.517,11.11) 99(18.597,11.51) 100(15.517,11.51) 101(-15.517,-8.09) 102(-18.597,-8.09) 103(-15.517,-7.69) 104(-18.597,-7.69) 105(-15.517,-7.29) 106(-18.597,-7.29) 107(-15.517,-6.89) 108(-18.597,-6.89) 109(-15.517,-6.49) 110(-18.597,-6.49) 111(-15.517,-6.09) 112(-18.597,-6.09) 113(-15.517,-5.69) 114(-18.597,-5.69) 115(-15.517,-5.29) 116(-18.597,-5.29) 117(-15.517,-4.89) 118(-18.597,-4.89) 119(-15.517,-4.49) 120(-18.597,-4.49) 121(-15.517,-4.09) 122(-18.597,-4.09) 123(-15.517,-3.69) 124(-18.597,-3.69) 125(-15.517,-3.29) 126(-18.597,-3.29) 127(-15.517,-2.89) 128(-18.597,-2.89) 129(-15.517,-2.49) 130(-18.597,-2.49) 131(-15.517,-2.09) 132(-18.597,-2.09) 133(-15.517,-1.69) 134(-18.597,-1.69) 135(-15.517,-1.29) 136(-18.597,-1.29) 137(-15.517,-0.89) 138(-18.597,-0.89) 139(-15.517,-0.49) 140(-18.597,-0.49) 141(-15.517,-0.09) 142(-18.597,-0.09) 143(-15.517,0.31) 144(-18.597,0.31) 145(-15.517,0.71) 146(-18.597,0.71) 147(-15.517,1.11) 148(-18.597,1.11) 149(-15.517,1.51) 150(-18.597,1.51) 151(-15.517,1.91) 152(-18.597,1.91) 153(-15.517,2.31) 154(-18.597,2.31) 155(-15.517,2.71) 156(-18.597,2.71) 157(-15.517,3.11) 158(-18.597,3.11) 159(-15.517,3.51) 160(-18.597,3.51) 161(-15.517,3.91) 162(-18.597,3.91) 163(-15.517,4.31) 164(-18.597,4.31) 165(-15.517,4.71) 166(-18.597,4.71) 167(-15.517,5.11) 168(-18.597,5.11) 169(-15.517,5.51) 170(-18.597,5.51) 171(-15.517,5.91) 172(-18.597,5.91) 173(-15.517,6.31) 174(-18.597,6.31) 175(-15.517,6.71) 176(-18.597,6.71) 177(-15.517,7.11) 178(-18.597,7.11) 179(-15.517,7.51) 180(-18.597,7.51) 181(-15.517,7.91) 182(-18.597,7.91) 183(-15.517,8.31) 184(-18.597,8.31) 185(-15.517,8.71) 186(-18.597,8.71) 187(-15.517,9.11) 188(-18.597,9.11) 189(-15.517,9.51) 190(-18.597,9.51) 191(-15.517,9.91) 192(-18.597,9.91) 193(-15.517,10.31) 194(-18.597,10.31) 195(-15.517,10.71) 196(-18.597,10.71) 197(-15.517,11.11) 198(-18.597,11.11) 199(-15.517,11.51) 200(-18.597,11.51)
  rect 0.2x0.7 smd mask+0: 201(9.845,21.67) 202(9.845,24.75) 203(9.445,21.67) 204(9.445,24.75) 205(9.045,21.67) 206(9.045,24.75) 207(8.645,21.67) 208(8.645,24.75) 209(8.245,21.67) 210(8.245,24.75) 211(7.845,21.67) 212(7.845,24.75) 213(7.445,21.67) 214(7.445,24.75) 215(7.045,21.67) 216(7.045,24.75) 217(6.645,21.67) 218(6.645,24.75) 219(6.245,21.67) 220(6.245,24.75) 221(5.845,21.67) 222(5.845,24.75) 223(5.445,21.67) 224(5.445,24.75) 225(5.045,21.67) 226(5.045,24.75) 227(4.645,21.67) 228(4.645,24.75) 229(4.245,21.67) 230(4.245,24.75) 231(3.845,21.67) 232(3.845,24.75) 233(3.445,21.67) 234(3.445,24.75) 235(3.045,21.67) 236(3.045,24.75) 237(2.645,21.67) 238(2.645,24.75) 239(2.245,21.67) 240(2.245,24.75) 241(1.845,21.67) 242(1.845,24.75) 243(1.445,21.67) 244(1.445,24.75) 245(1.045,21.67) 246(1.045,24.75) 247(0.645,21.67) 248(0.645,24.75) 249(0.245,21.67) 250(0.245,24.75) 251(-0.155,21.67) 252(-0.155,24.75) 253(-0.555,21.67) 254(-0.555,24.75) 255(-0.955,21.67) 256(-0.955,24.75) 257(-1.355,21.67) 258(-1.355,24.75) 259(-1.755,21.67) 260(-1.755,24.75) 261(-2.155,21.67) 262(-2.155,24.75) 263(-2.555,21.67) 264(-2.555,24.75) 265(-2.955,21.67) 266(-2.955,24.75) 267(-3.355,21.67) 268(-3.355,24.75) 269(-3.755,21.67) 270(-3.755,24.75) 271(-4.155,21.67) 272(-4.155,24.75) 273(-4.555,21.67) 274(-4.555,24.75) 275(-4.955,21.67) 276(-4.955,24.75) 277(-5.355,21.67) 278(-5.355,24.75) 279(-5.755,21.67) 280(-5.755,24.75) 281(-6.155,21.67) 282(-6.155,24.75) 283(-6.555,21.67) 284(-6.555,24.75) 285(-6.955,21.67) 286(-6.955,24.75) 287(-7.355,21.67) 288(-7.355,24.75) 289(-7.755,21.67) 290(-7.755,24.75) 291(-8.155,21.67) 292(-8.155,24.75) 293(-8.555,21.67) 294(-8.555,24.75) 295(-8.955,21.67) 296(-8.955,24.75) 297(-9.355,21.67) 298(-9.355,24.75) 299(-9.755,21.67) 300(-9.755,24.75)
  round 2.7 hole 2.7 paste-2539.97 mask+1.7: Un2(-16.553,-24.749) Un3(-16.573,23.201) Un4(16.447,-24.749) ""(16.427,23.201)
  silkscreen extent -20.05,-28.25 19.97,26.73

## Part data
C1 C2: Tolerance=10%, Voltage=>10V
H1 H2 J3: library part "DF40-100DS RCPT_1", "100 Position Connector Receptacle, Center Strip Contacts Surface Mount Gold", LCSC PN=C597931, Package=None, Supplier Part Number 1=DF40C-100DS-0.4V(5
HA HB: library part "DF40-XX-100DS RCPT", "100 Position Connector Receptacle, Center Strip Contacts Surface Mount Gold", LCSC PN=C19089239, Package=None, Supplier Part Number 1=DF40C-100DS-0.4V(5
R1 R2 R3 R4: Power=1/10W, Tolerance=1%
rPI1: library part RP-CM5-Rep, "Compute Module 5 adapter Footprint / Overlap Hirose 100P connector over pads to place actual components"
rxPI1: library part RX-CM5, "Radxa Compute Module 5 Footprint / Overlap Hirose 100P connector over pads to place actual components"
U1 U2: library part FSUSB42MUX, "FSUSB42 Series DPDT 4.3 V 480 Mbps SMT Hi Speed USB 2.0 Switch - MSOP-10", LCSC PN=C11355, Package="MSOP-10 ON Semiconductor", Supplier Part Number 1=FSUSB42MUXCT-ND
U3: library part TMUXHS4212IRKSR, "2-channel 16-Gbps 2:1/1:2 differential mux/demux", LCSC PN=C2869871, Mfr_Name="Texas Instruments", Supplier Part Number 1=595-TMUXHS4212RKSR

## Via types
v1: diameter 19.68, hole 11.81, Top Layer to Bottom Layer, 196 vias

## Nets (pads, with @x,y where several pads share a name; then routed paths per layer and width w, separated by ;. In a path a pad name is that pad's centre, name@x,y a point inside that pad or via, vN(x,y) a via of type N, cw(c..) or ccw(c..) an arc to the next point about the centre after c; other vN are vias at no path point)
5VDC_BUS: H1.77 H1.79 H1.81 H1.83 H1.85 H1.87 HA.78 HA.80 HA.82 HA.84 HA.86 HA.88 rPI1.77 rPI1.79 rPI1.81 rPI1.83 rPI1.85 rPI1.87 rxPI1.77 rxPI1.79 rxPI1.81 rxPI1.83 rxPI1.85 rxPI1.87 | length 511.1
  Top Layer w6.3: rxPI1.87@799.85,1742.17 799.95,1742.07 799.95,1696.16 v1(800.04,1696.06) ; H1.85@815.79,1739.81 v1(815.79,1780.71) ; rxPI1.83@831.35,1742.17 831.44,1742.07 831.44,1696.16 v1(831.54,1696.06) ; rxPI1.81@847.1,1742.17 847.19,1742.26 847.19,1780.62 v1(847.28,1780.71) ; rxPI1.79@862.84,1742.17 862.94,1742.07 862.94,1696.16 v1(863.03,1696.06) ; rxPI1.77@878.59,1742.17 878.69,1742.26 878.69,1780.62 v1(878.78,1780.71)
  Bottom Layer w6.3: rPI1.87@799.85,1742.17 799.85,1725.24 800.04,1725.05 v1(800.04,1696.06) ; rPI1.85@815.6,1742.17 815.6,1759.1 815.79,1759.28 v1(815.79,1780.71) ; rPI1.83@831.35,1742.17 831.35,1725.24 831.54,1725.05 v1(831.54,1696.06) ; rPI1.81@847.1,1742.17 847.1,1759.1 847.28,1759.28 v1(847.28,1780.71) ; rPI1.79@862.84,1742.17 862.84,1725.24 863.03,1725.05 v1(863.03,1696.06) ; rPI1.77@878.59,1742.17 878.59,1759.1 878.78,1759.28 v1(878.78,1780.71)
GND: H1.1 H1.2 H1.7 H1.8 H1.13 H1.14 H1.22 H1.23 H1.32 H1.33 H1.42 H1.43 H1.52 H1.53 H1.60 H1.65 H1.66 H1.71 H1.74 H1.98 H2.7 H2.8 H2.13 H2.14 H2.19 H2.20 H2.25 H2.26 H2.31 H2.32 H2.37 H2.38 H2.44 H2.50 H2.55 H2.56 H2.61 H2.62 H2.67 H2.68 H2.73 H2.74 H2.79 H2.80 H2.85 H2.86 H2.91 H2.92 H2.97 H2.98 HA.1 HA.2 HA.7 HA.8 HA.13 HA.14 HA.21 HA.24 HA.31 HA.34 HA.41 HA.44 HA.51 HA.54 HA.59 HA.65 HA.66 HA.72 HA.73 HA.97 HB.7 HB.8 HB.13 HB.14 HB.19 HB.20 HB.25 HB.26 HB.31 HB.32 HB.37 HB.38 HB.43 HB.49 HB.55 HB.56 HB.61 HB.62 HB.67 HB.68 HB.73 HB.74 HB.79 HB.80 HB.85 HB.86 HB.91 HB.92 HB.97 HB.98 J3.1 J3.2 J3.8 J3.14 J3.20 J3.21 J3.26 J3.31 J3.32 J3.38 J3.41 J3.44 J3.47 J3.50 J3.55 J3.56 J3.61 J3.62 J3.67 J3.68 J3.71 J3.74 J3.75 J3.99 J3.100 R1.2 R2.2 rPI1.1 rPI1.2 rPI1.7 rPI1.8 rPI1.13 rPI1.14 rPI1.22 rPI1.23 rPI1.32 rPI1.33 rPI1.42 rPI1.43 rPI1.52 rPI1.53 rPI1.60 rPI1.65 rPI1.66 rPI1.71 rPI1.74 rPI1.98 rPI1.107 rPI1.108 rPI1.113 rPI1.114 rPI1.119 rPI1.120 rPI1.125 rPI1.126 rPI1.131 rPI1.132 rPI1.137 rPI1.138 rPI1.144 rPI1.150 rPI1.155 rPI1.156 rPI1.161 rPI1.162 rPI1.167 rPI1.168 rPI1.173 rPI1.174 rPI1.179 rPI1.180 rPI1.185 rPI1.186 rPI1.191 rPI1.192 rPI1.197 rPI1.198 rxPI1.1 rxPI1.2 rxPI1.7 rxPI1.8 rxPI1.13 rxPI1.14 rxPI1.22 rxPI1.23 rxPI1.32 rxPI1.33 rxPI1.42 rxPI1.43 rxPI1.52 rxPI1.53 rxPI1.60 rxPI1.65 rxPI1.66 rxPI1.71 rxPI1.74 rxPI1.98 rxPI1.107 rxPI1.108 rxPI1.113 rxPI1.114 rxPI1.119 rxPI1.120 rxPI1.125 rxPI1.126 rxPI1.131 rxPI1.132 rxPI1.137 rxPI1.138 rxPI1.144 rxPI1.150 rxPI1.155 rxPI1.156 rxPI1.161 rxPI1.162 rxPI1.167 rxPI1.168 rxPI1.173 rxPI1.174 rxPI1.179 rxPI1.180 rxPI1.185 rxPI1.186 rxPI1.191 rxPI1.192 rxPI1.197 rxPI1.198 rxPI1.201 rxPI1.202 rxPI1.207 rxPI1.213 rxPI1.219 rxPI1.222 rxPI1.225 rxPI1.231 rxPI1.232 rxPI1.237 rxPI1.242 rxPI1.243 rxPI1.248 rxPI1.249 rxPI1.255 rxPI1.256 rxPI1.261 rxPI1.262 rxPI1.267 rxPI1.268 rxPI1.272 rxPI1.273 rxPI1.276 rxPI1.299 rxPI1.300 U1.5 U1.10 U2.5 U2.10 U3.2 U3.5 U3.11 U3.20 U3.21 | length 6607.4
  Top Layer w6: J3.99@184.13,625.95 J3.100@305.39,625.95 ; J3.75@184.13,814.93 216.14,814.93 231.88,830.68 J3.74@305.39,830.68 ; J3.71@184.13,846.43 229.48,846.43 260.98,877.92 J3.68@305.39,877.92 ; J3.67@184.13,877.92 221.61,877.92 268.85,925.17 J3.62@305.39,925.17 ; J3.61@184.13,925.17 221.61,925.17 268.85,972.41 J3.56@305.39,972.41 ; J3.55@184.13,972.41 221.61,972.41 268.85,1019.66 J3.50@305.39,1019.66 ; J3.47@184.13,1035.4 229.48,1035.4 260.98,1066.9 J3.44@305.39,1066.9 ; J3.41@184.13,1082.65 229.48,1082.65 260.98,1114.14 J3.38@305.39,1114.14 ; J3.31@184.13,1161.39 J3.32@305.39,1161.39 ; J3.21@184.13,1240.13 212.51,1240.13 ; J3.26@305.39,1208.63 260.98,1208.63 229.48,1240.13 212.51,1240.13 ; J3.20@305.39,1255.88 228.26,1255.88 212.51,1240.13 ; J3.14@305.39,1303.12 275.51,1303.12 212.51,1240.13 ; J3.8@305.39,1350.36 267.92,1350.36 220.67,1397.61 J3.1@184.13,1397.61 J3.2@305.39,1397.61 ; H2.73@910.09,399.09 910.09,369.91 924.49,355.51 v1(957.52,355.51) ; H2.44@1146.31,277.83 1146.31,306.31 1160.08,320.08 1193.74,320.08 1193.82,320 1230,320 1240.8,309.2 H2.32@1240.8,277.83
  Top Layer w6.3: H2.97@721.11,399.09 H2.97@721.11,399.09 ; v1(721.11,1660.63) 721.21,1660.54 721.21,1618.65 H1.98@721.3,1618.55 ; H2.98@721.3,276.9 v1(721.3,320.08) ; H2.91@768.36,399.09 768.45,399 768.45,355.61 v1(768.54,355.51) ; v1(768.54,233.46) H2.92@768.54,276.9 ; H2.85@815.6,399.09 815.69,399.19 815.69,442.03 v1(815.79,442.13) ; H2.86@815.79,276.9 v1(815.79,320.08) ; H2.79@862.84,399.09 862.94,399 862.94,355.61 v1(863.03,355.51) ; v1(863.03,233.46) H2.80@863.03,276.9 ; H2.73@910.09,399.09 H2.73@910.18,399.19 ; rxPI1.74@910.09,1620.91 v1(910.09,1660.63) ; H2.74@910.28,276.9 v1(910.28,320.08) ; rxPI1.71@925.84,1742.17 925.93,1742.07 925.93,1696.16 v1(926.02,1696.06) ; H2.67@957.33,399.09 957.43,399 957.43,355.61 v1(957.52,355.51) ; v1(957.52,233.46) H2.68@957.52,276.9 ; rxPI1.66@973.08,1620.91 973.17,1621 973.17,1660.54 v1(973.27,1660.63) ; rxPI1.65@973.08,1742.17 973.17,1742.26 973.17,1780.62 v1(973.27,1780.71) ; H2.61@1004.58,399.09 1004.67,399.19 1004.67,442.03 v1(1004.76,442.13) ; H2.62@1004.76,276.9 v1(1004.76,320.08) ; rxPI1.60@1020.32,1620.91 1020.42,1620.81 1020.42,1574.11 v1(1020.51,1574.02) ; H2.56@1051.82,277.83 1051.91,277.74 1051.91,233.56 v1(1052.01,233.46) ; v1(1052.01,355.51) 1051.91,355.61 1051.91,398.07 H2.55@1052.01,398.16 ; H1.53@1067.76,1739.81 v1(1067.76,1780.71) ; rxPI1.52@1083.32,1620.91 1083.41,1620.81 1083.41,1574.11 v1(1083.5,1574.02) ; H2.50@1099.25,276.9 v1(1099.25,320.08) ; H2.44@1146.31,277.83 H2.44@1146.4,277.74 ; v1(1146.5,1696.06) H1.43@1146.5,1739.81 ; rxPI1.42@1162.06,1620.91 1162.15,1621 1162.15,1660.54 v1(1162.24,1660.63) ; H2.38@1193.55,277.83 1193.65,277.93 1193.65,319.99 1193.74,320.08 ; H2.37@1193.55,399.09 1193.65,399.19 1193.65,442.03 1193.74,442.13 ; rxPI1.33@1225.05,1742.17 1225.14,1742.26 1225.14,1780.62 v1(1225.24,1780.71) ; H2.32@1240.8,277.83 H2.32@1240.89,277.74 ; H2.31@1240.8,399.09 1240.89,399 1240.89,355.61 1240.98,355.51 ; v1(1240.98,1574.02) H1.32@1240.98,1618.55 ; H2.26@1288.04,277.83 1288.13,277.93 1288.13,319.99 v1(1288.23,320.08) ; H2.25@1288.23,398.16 1288.23,442.13 ; v1(1303.98,1696.06) H1.23@1303.98,1739.81 ; H1.22@1319.72,1618.55 v1(1319.72,1660.63) ; H2.20@1335.29,277.83 1335.38,277.74 1335.38,233.56 v1(1335.47,233.46) ; v1(1335.47,355.51) H2.19@1335.47,398.16 ; v1(1366.97,442.13) 1382.62,426.47 H2.13@1382.62,399.19 ; H2.14@1382.53,277.83 1382.62,277.93 1382.62,319.99 v1(1382.72,320.08) ; rxPI1.13@1382.53,1742.17 1382.62,1742.26 1382.62,1780.62 v1(1382.72,1780.71) ; H1.14@1382.72,1618.55 v1(1382.72,1660.63) ; H2.8@1429.77,277.83 1429.87,277.74 1429.87,233.56 v1(1429.96,233.46) ; rxPI1.7@1429.77,1742.17 1429.87,1742.07 1429.87,1696.16 v1(1429.96,1696.06) ; v1(1429.96,1574.02) H1.8@1429.96,1618.55 ; rxPI1.1@1477.02,1742.17 1477.11,1742.26 1477.11,1780.62 v1(1477.2,1780.71) ; H1.2@1477.2,1618.55 v1(1477.2,1660.63)
  Bottom Layer w6: U3.2@526.69,1230.32 528.81,1232.43 545.94,1232.43 573.35,1259.84 583.19,1250 U3.20@583.19,1213.19 ; U3.5@526.69,1289.37 563.5,1289.37 v1(573.35,1299.21) 573.35,1338.58 583.19,1348.43 U3.11@583.19,1385.24 ; HB.74@910.28,390.88 910.28,369.72 924.49,355.51 v1(957.52,355.51) ; HB.43@1146.5,284.18 1146.5,306.5 1160.08,320.08 1193.74,320.08 ; 1193.98,319.84 1230.16,319.84 1240.98,309.02 HB.31@1240.98,284.18 ; 1247.73,770.63 U2.5@1312.87,770.63 1312.87,746.08 ; U1.10@1447.13,829.37 1513.94,829.37 ; v1(1612.87,720) U1.5@1612.87,750.63 1659.28,750.63
  Bottom Layer w6.3: rPI1.198@721.11,277.83 721.11,294.76 721.3,294.95 v1(721.3,320.08) ; rPI1.98@721.11,1620.91 v1(721.11,1660.63) ; rPI1.192@768.36,277.83 768.36,260.9 768.54,260.72 v1(768.54,233.46) ; v1(768.54,355.51) HB.92@768.54,390.88 ; HB.85@815.79,284.18 v1(815.79,320.08) ; HB.86@815.79,390.88 v1(815.79,442.13) ; rPI1.180@862.84,277.83 862.84,260.9 863.03,260.72 v1(863.03,233.46) ; v1(863.03,355.51) HB.80@863.03,390.88 ; rPI1.174@910.09,277.83 910.09,294.76 910.28,294.95 v1(910.28,320.08) ; rPI1.74@910.09,1620.91 v1(910.09,1660.63) ; v1(926.02,1696.06) HA.72@926.02,1732.53 ; rPI1.168@957.33,277.83 957.33,260.9 957.52,260.72 v1(957.52,233.46) ; v1(957.52,355.51) HB.68@957.52,390.88 ; HA.65@973.27,1625.84 v1(973.27,1660.63) ; HA.66@973.27,1732.53 v1(973.27,1780.71) ; rPI1.162@1004.58,277.83 1004.58,294.76 1004.76,294.95 v1(1004.76,320.08) ; HB.62@1004.76,390.88 v1(1004.76,442.13) ; rPI1.60@1020.32,1620.91 1020.32,1603.98 1020.51,1603.79 v1(1020.51,1574.02) ; rPI1.156@1051.82,277.83 1051.82,260.9 1052.01,260.72 v1(1052.01,233.46) ; v1(1052.01,355.51) HB.56@1052.01,390.88 ; HA.54@1067.76,1732.53 v1(1067.76,1780.71) ; rPI1.52@1083.32,1620.91 1083.32,1574.2 v1(1083.5,1574.02) ; rPI1.150@1099.06,277.83 1099.06,294.76 1099.25,294.95 v1(1099.25,320.08) ; rPI1.43@1146.31,1742.17 1146.31,1696.25 v1(1146.5,1696.06) ; rPI1.42@1162.06,1620.91 1162.06,1660.44 v1(1162.24,1660.63) ; HB.37@1193.74,284.18 1193.74,320.08 ; HB.38@1193.74,390.88 1193.74,442.13 ; rPI1.33@1225.05,1742.17 1225.05,1780.52 v1(1225.24,1780.71) ; rPI1.32@1240.8,1620.91 1240.8,1574.2 v1(1240.98,1574.02) ; 1240.98,355.51 HB.32@1240.98,390.88 ; rPI1.126@1288.04,277.83 1288.04,319.89 v1(1288.23,320.08) ; HB.26@1288.23,390.88 1288.23,442.13 ; rPI1.23@1303.79,1742.17 1303.79,1696.25 v1(1303.98,1696.06) ; rPI1.22@1319.54,1620.91 1319.54,1660.44 v1(1319.72,1660.63) ; rPI1.120@1335.29,277.83 1335.29,233.65 v1(1335.47,233.46) ; rPI1.119@1335.29,399.09 1335.29,355.7 v1(1335.47,355.51) ; v1(1366.97,442.13) 1382.53,426.57 rPI1.113@1382.53,399.09 ; rPI1.13@1382.53,1742.17 1382.53,1780.52 v1(1382.72,1780.71) ; HB.13@1382.72,284.18 v1(1382.72,320.08) ; HA.13@1382.72,1625.84 v1(1382.72,1660.63) ; rPI1.108@1429.77,277.83 1429.77,233.65 v1(1429.96,233.46) ; rPI1.7@1429.77,1742.17 1429.77,1696.25 v1(1429.96,1696.06) ; v1(1429.96,1574.02) HA.7@1429.96,1625.84 ; rPI1.1@1477.02,1742.17 1477.02,1780.52 v1(1477.2,1780.71) ; HA.1@1477.2,1625.84 v1(1477.2,1660.63)
HDMI0_CEC: H2.51 HB.52 rPI1.151 rxPI1.151 | length 87.3
  Top Layer w6.3: H2.51@1083.32,399.09 1083.41,399 1083.41,355.61 v1(1083.5,355.51)
  Bottom Layer w6.3: rPI1.151@1083.32,399.09 1083.32,382.16 1083.5,381.98 v1(1083.5,355.51)
HDMI0_CLK_N: H2.90 HB.89 rPI1.190 rxPI1.190 | length 78.2
  Top Layer w6.3: H2.90@784.1,277.83 784.2,277.93 784.2,319.99 v1(784.29,320.08)
  Bottom Layer w6.3: HB.89@784.29,284.18 v1(784.29,320.08)
HDMI0_CLK_P: H2.88 HB.87 rPI1.188 rxPI1.188 | length 88.9
  Top Layer w6.3: H2.88@799.85,277.83 799.95,277.74 799.95,233.56 v1(800.04,233.46)
  Bottom Layer w6.3: rPI1.188@799.85,277.83 799.85,260.9 800.04,260.72 v1(800.04,233.46)
HDMI0_HOTPLUG: H2.53 HB.54 rPI1.153 rxPI1.153 | length 87.5
  Top Layer w6.3: H2.53@1067.57,399.09 1068.36,399.88 1068.36,441.24 v1(1069.25,442.13)
  Bottom Layer w6.3: rPI1.153@1067.57,399.09 1068.5,400.03 1068.5,441.38 v1(1069.25,442.13)
HDMI0_SCL: H2.100 HB.99 rPI1.200 rxPI1.200 | length 88.9
  Top Layer w6.3: H2.100@705.36,277.83 705.46,277.74 705.46,233.56 v1(705.55,233.46)
  Bottom Layer w6.3: rPI1.200@705.36,277.83 705.36,260.9 705.55,260.72 v1(705.55,233.46)
HDMI0_SDA: H2.99 HB.100 rPI1.199 rxPI1.199 | length 79
  Top Layer w6.3: H2.99@705.36,399.09 705.46,399 705.46,355.61 v1(705.55,355.51)
  Bottom Layer w6.3: v1(705.55,355.51) HB.100@705.55,390.88
HDMI0_TX0_N: H2.84 HB.83 rPI1.184 rxPI1.184 | length 95.2
  Top Layer w6.3: H2.84@831.35,277.83 831.44,277.74 831.44,233.56 v1(831.54,233.46)
  Bottom Layer w6.3: v1(831.54,233.46) HB.83@831.54,284.18
HDMI0_TX0_P: H2.82 HB.81 rPI1.182 rxPI1.182 | length 85.5
  Top Layer w6.3: H2.82@847.28,276.9 v1(847.28,320.08)
  Bottom Layer w6.3: rPI1.182@847.1,277.83 847.1,294.76 847.28,294.95 v1(847.28,320.08)
HDMI0_TX1_N: H2.78 HB.77 rPI1.178 rxPI1.178 | length 85.5
  Top Layer w6.3: H2.78@878.78,276.9 v1(878.78,320.08)
  Bottom Layer w6.3: rPI1.178@878.59,277.83 878.59,294.76 878.78,294.95 v1(878.78,320.08)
